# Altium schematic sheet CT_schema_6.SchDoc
size 373 x 245 mm
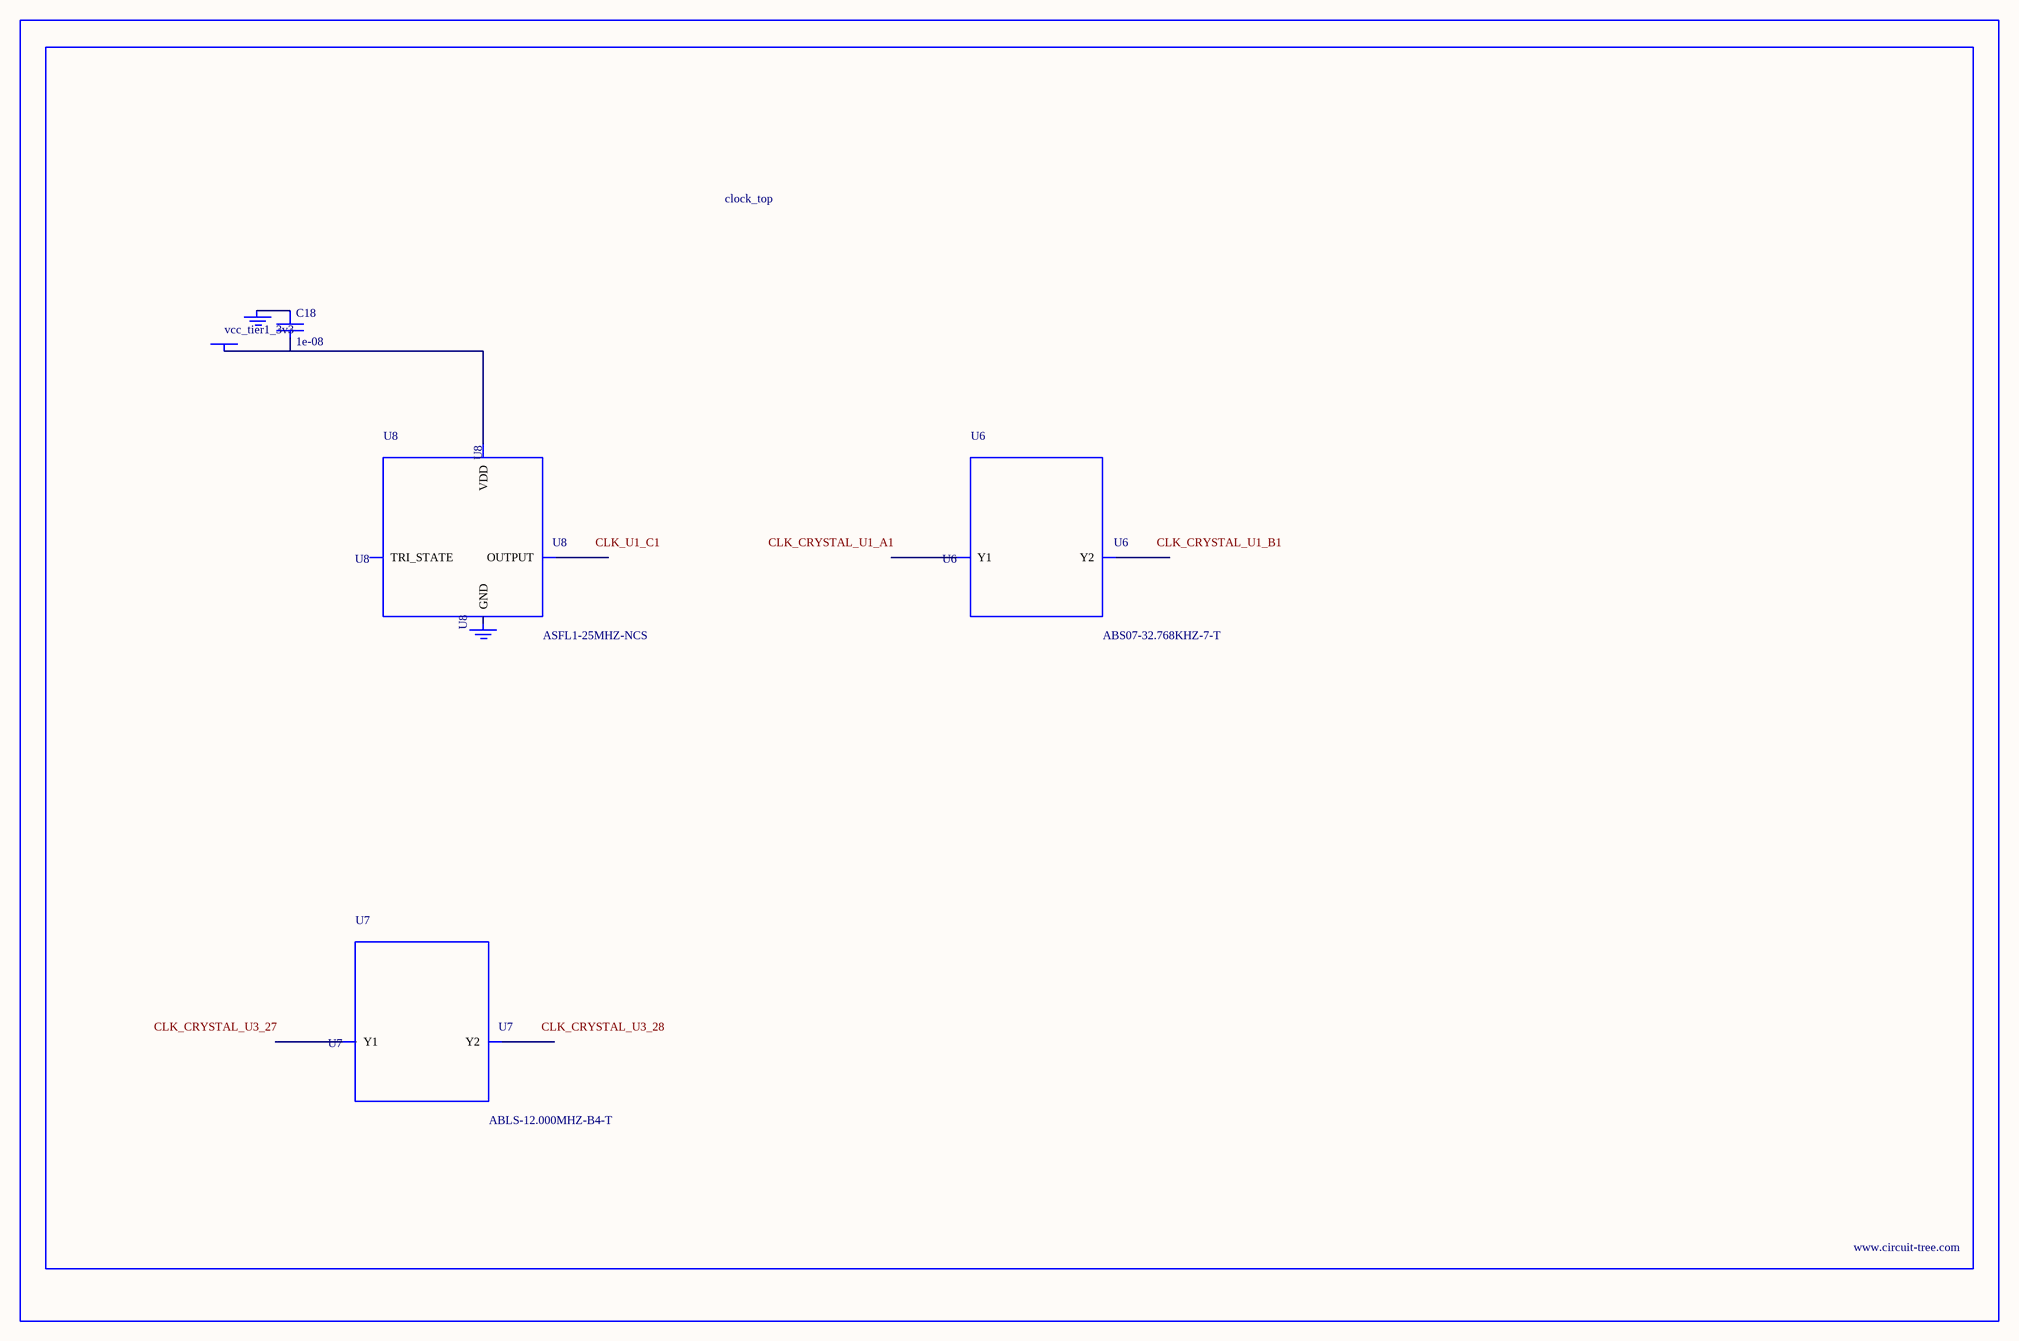
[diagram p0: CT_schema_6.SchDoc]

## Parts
BORDER5  (no value)
C18  1e-08  [C0402]
GND_INSTANCE_5_0  (no value)
GND_INSTANCE_5_1  (no value)
POWER_INSTANCE_5_0  vcc_tier1_3v3
U6  ABS07-32.768KHZ-7-T  [ABS07-32.768KHZ-7-T]
U7  ABLS-12.000MHZ-B4-T  [ABLS-12.000MHZ-B4-T]
U8  ASFL1-25MHZ-NCS  [ASFL1]

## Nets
NetC18_1: C18.1 GND_INSTANCE_5_0.0(GND)
NetC18_2: C18.2 POWER_INSTANCE_5_0.0(PWR) U8.4(VDD)

Not connected (* = marked no-connect by the designer): GND_INSTANCE_5_1 0(GND); U6 1(Y1) 2(Y2); U7 1(Y1) 2(Y2); U8 1(TRI_STATE) 2(GND) 3(OUTPUT)

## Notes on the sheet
- Labels drawn without touching a wire or pin: CLK_CRYSTAL_U1_A1, CLK_CRYSTAL_U1_B1, CLK_CRYSTAL_U3_27, CLK_CRYSTAL_U3_28, CLK_U1_C1

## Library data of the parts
BORDER5 = BORDER_PAGE5
C18 = C0402C103K3RAC
GND_INSTANCE_5_0 GND_INSTANCE_5_1 = GND
POWER_INSTANCE_5_0 = PWR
